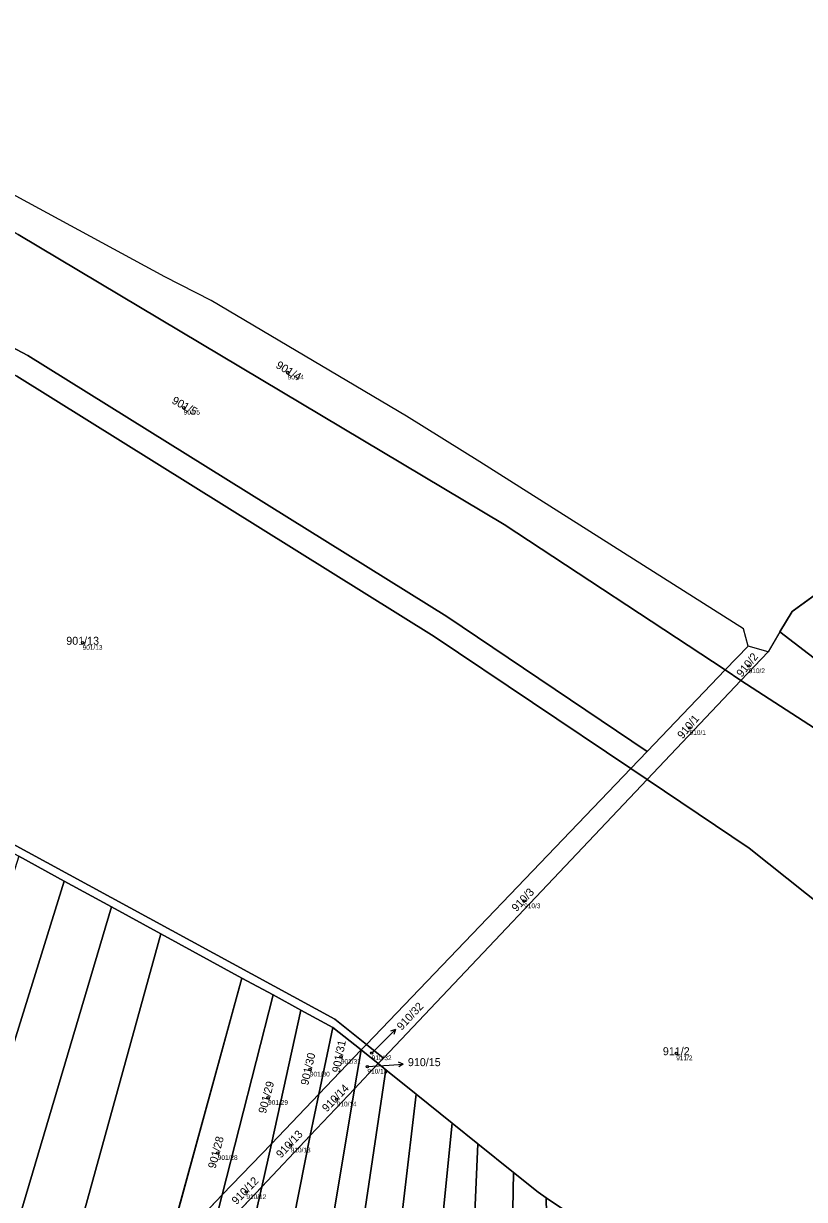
# Model space of a CAD drawing. Extents: x -603967 to -594699, y -1179315 to -1165625.
# Drawn here: x -596782.3 to -596616.5, y -1171481.1 to -1171231.3 of the extents above; entities that cross this region are included whole.
import ezdxf

# ---------------------------------------------------------------- set-up
doc = ezdxf.new("R2010")
doc.units = 0
for name, color, linetype in [('Definiční body', 7, 'Continuous'), ('Hranice parcel', 7, 'Continuous'), ('Parcelní čísla', 7, 'Continuous'), ('Polygon ku', 7, 'Continuous'), ('Polygon parcely', 7, 'Continuous'), ('Pop  PČ popisy', 7, 'Continuous')]:
    doc.layers.add(name, color=color, linetype=linetype)

msp = doc.modelspace()

# ---------------------------------------------------------------- linework, layer by layer
at = {"layer": 'Definiční body'}
for centre in [(-596726.2, -1171305.39994), (-596748.26, -1171312.85994), (-596769.73, -1171362.81994), (-596628.33, -1171367.77994), (-596640.87, -1171380.90994), (-596675.99, -1171417.69994), (-596714.9, -1171450.74994), (-596708.36, -1171449.97994), (-596643.71, -1171449.99994), (-596721.48, -1171453.43994), (-596709.26, -1171452.82994), (-596730.35, -1171459.46994), (-596715.78, -1171459.79994), (-596741.04, -1171471.16994), (-596725.55, -1171469.56994), (-596734.96, -1171479.47994)]:
    msp.add_circle(centre, 0.25, dxfattribs=at)
at = {"layer": 'Hranice parcel'}
for p, q in [((-596619.12, -1171356.19), (-596602.4, -1171344.02)), ((-596621.72, -1171360.51), (-596619.12, -1171356.19)), ((-596649.88, -1171385.89), (-596692.43, -1171357.23)), ((-596628.44, -1171363.52), (-596629.4, -1171359.89)), ((-596621.72, -1171360.51), (-596624.19, -1171364.74)), ((-596633.3, -1171368.58), (-596628.44, -1171363.52)), ((-596624.19, -1171364.74), (-596628.44, -1171363.52)), ((-596629.99, -1171370.85), (-596624.19, -1171364.74)), ((-596649.88, -1171385.89), (-596633.3, -1171368.58)), ((-596629.99, -1171370.85), (-596633.3, -1171368.58)), ((-596629.99, -1171370.85), (-596649.86, -1171391.85)), ((-596653.34, -1171389.51), (-596649.88, -1171385.89)), ((-596709.48, -1171448.14), (-596653.34, -1171389.51)), ((-596653.34, -1171389.51), (-596649.86, -1171391.85)), ((-596705.86, -1171451.05), (-596649.86, -1171391.85)), ((-596773.62, -1171413.45), (-596783.3, -1171408.17)), ((-596763.61, -1171418.91), (-596773.62, -1171413.45)), ((-596753.13, -1171424.63), (-596763.61, -1171418.91)), ((-596735.91, -1171434.02), (-596753.13, -1171424.63)), ((-596751.95, -1171492.5), (-596735.91, -1171434.02)), ((-596729.3, -1171437.63), (-596735.91, -1171434.02)), ((-596740.08, -1171480.1), (-596729.3, -1171437.63)), ((-596723.39, -1171440.85), (-596729.3, -1171437.63)), ((-596729.65, -1171469.21), (-596723.39, -1171440.85)), ((-596716.61, -1171444.55), (-596723.39, -1171440.85)), ((-596719.57, -1171458.68), (-596716.61, -1171444.55)), ((-596710.6, -1171449.31), (-596716.61, -1171444.55)), ((-596710.6, -1171449.31), (-596709.48, -1171448.14)), ((-596709.48, -1171448.14), (-596705.86, -1171451.05)), ((-596719.57, -1171458.68), (-596710.6, -1171449.31)), ((-596712.04, -1171457.58), (-596710.6, -1171449.31)), ((-596706.95, -1171452.2), (-596710.6, -1171449.31)), ((-596706.95, -1171452.2), (-596705.86, -1171451.05)), ((-596712.04, -1171457.58), (-596706.95, -1171452.2)), ((-596705.33, -1171453.51), (-596706.95, -1171452.2)), ((-596698.89, -1171458.69), (-596705.33, -1171453.51)), ((-596729.65, -1171469.21), (-596719.57, -1171458.68)), ((-596721.41, -1171467.49), (-596712.04, -1171457.58)), ((-596721.41, -1171467.49), (-596719.57, -1171458.68)), ((-596691.26, -1171464.85), (-596698.89, -1171458.69)), ((-596685.81, -1171469.25), (-596691.26, -1171464.85)), ((-596731.67, -1171478.34), (-596721.41, -1171467.49)), ((-596740.08, -1171480.1), (-596729.65, -1171469.21)), ((-596731.67, -1171478.34), (-596729.65, -1171469.21)), ((-596693.33, -1171641.5), (-596685.81, -1171469.25)), ((-596678.26, -1171475.33), (-596685.81, -1171469.25)), ((-596742.55, -1171489.84), (-596731.67, -1171478.34)), ((-596751.95, -1171492.5), (-596740.08, -1171480.1)), ((-596742.55, -1171489.84), (-596740.08, -1171480.1)), ((-596662.73, -1171486.46), (-596671.31, -1171480.7))]:
    msp.add_line(p, q, dxfattribs=at)
for points in [[(-596629.4, -1171359.89), (-596685.43, -1171324.38), (-596700.95, -1171314.68), (-596742.41, -1171290.11), (-596752.26, -1171285.09), (-596817.16, -1171249.9)], [(-596820.19, -1171255.5), (-596783.42, -1171276.1), (-596680.26, -1171337.71), (-596633.3, -1171368.58)], [(-596692.43, -1171357.23), (-596781.35, -1171301.79), (-596830.85, -1171275.6)], [(-596833.95, -1171279.61), (-596783.69, -1171306.21), (-596695.08, -1171361.47), (-596653.34, -1171389.51)], [(-596890.05, -1171348.16), (-596716.16, -1171442.76), (-596709.48, -1171448.14)], [(-596430.14, -1171521.48), (-596487.82, -1171467.23), (-596538.67, -1171424.28), (-596621.72, -1171360.51)], [(-596437.15, -1171526.89), (-596494.86, -1171471.93), (-596543.14, -1171431.06), (-596585.28, -1171399.79), (-596629.99, -1171370.85)], [(-596649.86, -1171391.85), (-596628.19, -1171406.41), (-596575.39, -1171448.54)], [(-596821.45, -1171565.08), (-596801.93, -1171504.41), (-596773.62, -1171413.45)], [(-596801.66, -1171544.41), (-596793, -1171517.97), (-596763.61, -1171418.91)], [(-596781.24, -1171523.09), (-596776.22, -1171508.26), (-596753.13, -1171424.63)], [(-596732.91, -1171640.89), (-596722.26, -1171567.29), (-596705.33, -1171453.51)], [(-596743.82, -1171640.72), (-596722.15, -1171518.4), (-596712.04, -1171457.58)], [(-596720.4, -1171641.08), (-596714.61, -1171592.07), (-596698.89, -1171458.69)], [(-596705.63, -1171641.31), (-596702.46, -1171590.54), (-596698.86, -1171540.39), (-596691.26, -1171464.85)], [(-596757.97, -1171640.5), (-596742.42, -1171570.24), (-596729.52, -1171508.31), (-596721.41, -1171467.49)], [(-596680.83, -1171641.69), (-596680.15, -1171581.38), (-596678.26, -1171475.33)], [(-596671.31, -1171480.7), (-596673.03, -1171479.54), (-596678.26, -1171475.33)], [(-596768.62, -1171640.34), (-596748.09, -1171550.26), (-596731.67, -1171478.34)], [(-596667.7, -1171641.89), (-596668.98, -1171589.93), (-596671.31, -1171480.7)]]:
    msp.add_lwpolyline(points, dxfattribs=at)
at = {"layer": 'Polygon ku'}
msp.add_lwpolyline([(-596602.4, -1171344.02), (-596619.12, -1171356.19), (-596621.72, -1171360.51), (-596624.19, -1171364.74), (-596628.44, -1171363.52), (-596629.4, -1171359.89), (-596685.43, -1171324.38), (-596700.95, -1171314.68), (-596742.41, -1171290.11), (-596752.26, -1171285.09), (-596817.16, -1171249.9), (-596848.83, -1171233.09), (-596852.18, -1171231.29), (-596853.76, -1171236.46), (-596855.37, -1171241.18), (-596856.84, -1171245.75), (-596862.88, -1171264.49), (-596871.71, -1171291.66), (-596879.49, -1171315.59), (-596890.05, -1171348.16), (-596890.56, -1171349.68), (-596922.48, -1171448.18), (-596974.71, -1171587.69)], dxfattribs=at)
at = {"layer": 'Polygon parcely'}
for points in [[(-596847.21, -1171272.6), (-596833.95, -1171279.61), (-596783.69, -1171306.21), (-596695.08, -1171361.47), (-596653.34, -1171389.51), (-596649.88, -1171385.89), (-596692.43, -1171357.23), (-596781.35, -1171301.79), (-596830.85, -1171275.6), (-596820.19, -1171255.5), (-596851.72, -1171237.61), (-596854.32, -1171241.75), (-596856.84, -1171245.75), (-596862.88, -1171264.49)], [(-596633.3, -1171368.58), (-596628.44, -1171363.52), (-596629.4, -1171359.89), (-596685.43, -1171324.38), (-596700.95, -1171314.68), (-596742.41, -1171290.11), (-596752.26, -1171285.09), (-596817.16, -1171249.9), (-596820.19, -1171255.5), (-596783.42, -1171276.1), (-596680.26, -1171337.71)], [(-596649.88, -1171385.89), (-596633.3, -1171368.58), (-596680.26, -1171337.71), (-596783.42, -1171276.1), (-596820.19, -1171255.5), (-596830.85, -1171275.6), (-596781.35, -1171301.79), (-596692.43, -1171357.23)], [(-596709.48, -1171448.14), (-596653.34, -1171389.51), (-596695.08, -1171361.47), (-596783.69, -1171306.21), (-596833.95, -1171279.61), (-596863.88, -1171325.7), (-596879.49, -1171315.59), (-596890.05, -1171348.16), (-596716.16, -1171442.76)], [(-596406.59, -1171503.29), (-596506.53, -1171415.83), (-596602.4, -1171344.02), (-596619.12, -1171356.19), (-596621.72, -1171360.51), (-596538.67, -1171424.28), (-596487.82, -1171467.23), (-596430.14, -1171521.48), (-596427.69, -1171519.58), (-596417.99, -1171512.1), (-596408.65, -1171504.88)], [(-596879.22, -1171355.86), (-596867.78, -1171362.1), (-596857.48, -1171367.72), (-596847.14, -1171373.36), (-596836.06, -1171379.4), (-596826.21, -1171384.77), (-596816.22, -1171390.22), (-596805.99, -1171395.8), (-596794.15, -1171402.25), (-596783.3, -1171408.17), (-596773.62, -1171413.45), (-596763.61, -1171418.91), (-596753.13, -1171424.63), (-596735.91, -1171434.02), (-596729.3, -1171437.63), (-596723.39, -1171440.85), (-596716.61, -1171444.55), (-596710.6, -1171449.31), (-596709.48, -1171448.14), (-596716.16, -1171442.76), (-596890.05, -1171348.16), (-596890.56, -1171349.68)], [(-596487.82, -1171467.23), (-596538.67, -1171424.28), (-596621.72, -1171360.51), (-596624.19, -1171364.74), (-596629.99, -1171370.85), (-596585.28, -1171399.79), (-596543.14, -1171431.06), (-596494.86, -1171471.93), (-596437.15, -1171526.89), (-596430.14, -1171521.48)], [(-596628.44, -1171363.52), (-596633.3, -1171368.58), (-596629.99, -1171370.85), (-596624.19, -1171364.74)], [(-596629.99, -1171370.85), (-596633.3, -1171368.58), (-596649.88, -1171385.89), (-596653.34, -1171389.51), (-596649.86, -1171391.85)], [(-596585.28, -1171399.79), (-596629.99, -1171370.85), (-596649.86, -1171391.85), (-596628.19, -1171406.41), (-596575.39, -1171448.54), (-596548.72, -1171466.95), (-596515.76, -1171491.6), (-596461.39, -1171545.57), (-596457.91, -1171542.88), (-596453.71, -1171539.65), (-596450.67, -1171537.31), (-596447.07, -1171534.54), (-596437.15, -1171526.89), (-596494.86, -1171471.93), (-596543.14, -1171431.06)], [(-596705.86, -1171451.05), (-596649.86, -1171391.85), (-596653.34, -1171389.51), (-596709.48, -1171448.14)], [(-596821.45, -1171565.08), (-596801.93, -1171504.41), (-596773.62, -1171413.45), (-596783.3, -1171408.17), (-596822.63, -1171532.86), (-596840.46, -1171585.24), (-596825.89, -1171569.72)], [(-596821.45, -1171565.08), (-596801.66, -1171544.41), (-596793, -1171517.97), (-596763.61, -1171418.91), (-596773.62, -1171413.45), (-596801.93, -1171504.41)], [(-596763.61, -1171418.91), (-596793, -1171517.97), (-596801.66, -1171544.41), (-596781.24, -1171523.09), (-596776.22, -1171508.26), (-596753.13, -1171424.63)], [(-596753.13, -1171424.63), (-596776.22, -1171508.26), (-596781.24, -1171523.09), (-596751.95, -1171492.5), (-596735.91, -1171434.02)], [(-596735.91, -1171434.02), (-596751.95, -1171492.5), (-596740.08, -1171480.1), (-596729.3, -1171437.63)], [(-596729.3, -1171437.63), (-596740.08, -1171480.1), (-596729.65, -1171469.21), (-596723.39, -1171440.85)], [(-596723.39, -1171440.85), (-596729.65, -1171469.21), (-596719.57, -1171458.68), (-596716.61, -1171444.55)], [(-596716.61, -1171444.55), (-596719.57, -1171458.68), (-596710.6, -1171449.31)], [(-596706.95, -1171452.2), (-596705.86, -1171451.05), (-596709.48, -1171448.14), (-596710.6, -1171449.31)], [(-596712.04, -1171457.58), (-596710.6, -1171449.31), (-596719.57, -1171458.68), (-596721.41, -1171467.49)], [(-596712.04, -1171457.58), (-596706.95, -1171452.2), (-596710.6, -1171449.31)], [(-596733.85, -1171640.88), (-596732.91, -1171640.89), (-596722.26, -1171567.29), (-596705.33, -1171453.51), (-596706.95, -1171452.2), (-596712.04, -1171457.58), (-596722.15, -1171518.4), (-596743.82, -1171640.72)], [(-596705.33, -1171453.51), (-596722.26, -1171567.29), (-596732.91, -1171640.89), (-596725.01, -1171641.01), (-596720.4, -1171641.08), (-596714.61, -1171592.07), (-596698.89, -1171458.69)], [(-596743.82, -1171640.72), (-596722.15, -1171518.4), (-596712.04, -1171457.58), (-596721.41, -1171467.49), (-596729.52, -1171508.31), (-596742.42, -1171570.24), (-596757.97, -1171640.5), (-596751.75, -1171640.6)], [(-596721.41, -1171467.49), (-596719.57, -1171458.68), (-596729.65, -1171469.21), (-596731.67, -1171478.34)], [(-596698.89, -1171458.69), (-596714.61, -1171592.07), (-596720.4, -1171641.08), (-596715.61, -1171641.15), (-596706.66, -1171641.29), (-596705.63, -1171641.31), (-596702.46, -1171590.54), (-596698.86, -1171540.39), (-596691.26, -1171464.85)], [(-596698.11, -1171641.43), (-596693.33, -1171641.5), (-596685.81, -1171469.25), (-596691.26, -1171464.85), (-596698.86, -1171540.39), (-596702.46, -1171590.54), (-596705.63, -1171641.31)], [(-596757.97, -1171640.5), (-596742.42, -1171570.24), (-596729.52, -1171508.31), (-596721.41, -1171467.49), (-596731.67, -1171478.34), (-596748.09, -1171550.26), (-596768.62, -1171640.34)], [(-596731.67, -1171478.34), (-596729.65, -1171469.21), (-596740.08, -1171480.1), (-596742.55, -1171489.84)], [(-596685.81, -1171469.25), (-596693.33, -1171641.5), (-596688.26, -1171641.58), (-596680.83, -1171641.69), (-596680.15, -1171581.38), (-596678.26, -1171475.33)], [(-596671.46, -1171641.83), (-596667.7, -1171641.89), (-596668.98, -1171589.93), (-596671.31, -1171480.7), (-596673.03, -1171479.54), (-596678.26, -1171475.33), (-596680.15, -1171581.38), (-596680.83, -1171641.69)], [(-596748.09, -1171550.26), (-596731.67, -1171478.34), (-596742.55, -1171489.84), (-596765.13, -1171577.48), (-596783.49, -1171640.11), (-596768.62, -1171640.34)], [(-596742.55, -1171489.84), (-596740.08, -1171480.1), (-596751.95, -1171492.5), (-596754.76, -1171502.75)], [(-596671.31, -1171480.7), (-596668.98, -1171589.93), (-596667.7, -1171641.89), (-596666.17, -1171641.91), (-596655.52, -1171642.08), (-596657.59, -1171577.64), (-596662.73, -1171486.46)]]:
    msp.add_lwpolyline(points, close=True, dxfattribs=at)
msp.add_lwpolyline([(-596614.68, -1171487.54), (-596606.58, -1171480.19), (-596604.56, -1171478.61), (-596593.24, -1171469.76), (-596591.42, -1171467.6), (-596575.39, -1171448.54), (-596628.19, -1171406.41), (-596649.86, -1171391.85), (-596705.86, -1171451.05), (-596706.95, -1171452.2), (-596705.33, -1171453.51), (-596698.89, -1171458.69), (-596691.26, -1171464.85), (-596685.81, -1171469.25), (-596678.26, -1171475.33), (-596673.03, -1171479.54), (-596671.31, -1171480.7), (-596662.73, -1171486.46)], dxfattribs=at)
at = {"layer": 'Pop  PČ popisy'}
for p, q in [((-596705.42, -1171447.07), (-596703.298, -1171444.948)), ((-596703.298, -1171444.948), (-596704.36, -1171445.302)), ((-596703.298, -1171444.948), (-596703.652, -1171446.01)), ((-596708.36, -1171449.98), (-596705.42, -1171447.07)), ((-596709.26, -1171452.83), (-596704.66, -1171452.52)), ((-596704.66, -1171452.52), (-596701.666, -1171452.311)), ((-596701.666, -1171452.311), (-596702.7, -1171451.881)), ((-596701.666, -1171452.311), (-596702.63, -1171452.88))]:
    msp.add_line(p, q, dxfattribs=at)

# ---------------------------------------------------------------- texts
at = {"layer": 'Definiční body'}
for s, p in [('901/4', (-596726.2, -1171306.889)), ('901/5', (-596748.26, -1171314.349)), ('901/13', (-596769.73, -1171364.309)), ('910/2', (-596628.33, -1171369.269)), ('910/1', (-596640.87, -1171382.399)), ('910/3', (-596675.99, -1171419.189)), ('901/31', (-596714.9, -1171452.239)), ('910/32', (-596708.36, -1171451.469)), ('911/2', (-596643.71, -1171451.489)), ('910/15', (-596709.26, -1171454.319)), ('901/30', (-596721.48, -1171454.929)), ('901/29', (-596730.35, -1171460.959)), ('910/14', (-596715.78, -1171461.289)), ('910/13', (-596725.55, -1171471.059)), ('901/28', (-596741.04, -1171472.659)), ('910/12', (-596734.96, -1171480.969))]:
    msp.add_text(s, height=0.999996, dxfattribs=at).set_placement(p)
at = {"layer": 'Parcelní čísla'}
for s, rotation, p in [('901/4', 329, (-596728.849, -1171304.303)), ('901/5', 331, (-596750.946, -1171311.856)), ('910/2', 51, (-596629.784, -1171370.251)), ('910/1', 50, (-596642.367, -1171383.355)), ('910/3', 47, (-596677.613, -1171420.064)), ('910/32', 47, (-596701.979, -1171445.249)), ('901/31', 79, (-596715.144, -1171454.233)), ('901/30', 77, (-596721.845, -1171456.913)), ('901/29', 75, (-596730.836, -1171462.928)), ('910/14', 46, (-596717.882, -1171462.588)), ('901/28', 75, (-596741.526, -1171474.628)), ('910/13', 47, (-596727.603, -1171472.395)), ('910/12', 46, (-596737.062, -1171482.268))]:
    msp.add_text(s, height=1.699998, rotation=rotation, dxfattribs=at).set_placement(p)
for s, p in [('901/13', (-596773.196, -1171363.245)), ('911/2', (-596646.546, -1171450.425)), ('910/15', (-596700.67, -1171452.745))]:
    msp.add_text(s, height=1.699998, dxfattribs=at).set_placement(p)

doc.saveas('drawing.dxf')
